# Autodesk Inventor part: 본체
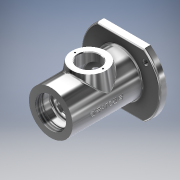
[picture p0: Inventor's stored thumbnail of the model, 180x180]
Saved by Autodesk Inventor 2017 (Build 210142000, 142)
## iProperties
Part Number: 본체
Material: 알루미늄 6061
Document SubType Name: Modeling
Designer: MRC
Density: 2.7 g/cm^3
Appearance: 알루미늄 - 평지
Mass: 701.516 g
Surface Area: 611.613 cm^2
Volume: 259.821 cm^3
Author: MRC
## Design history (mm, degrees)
sketch "스케치1"
  geometry: C1 r 32 at (0, 0); 1 further point
  constraints: 1 centre point, 1 coincident
  dimensions: "d0" = 64 diameter of C1
extrude "돌출1" new body sketch "스케치1" distance "d1" = 102; taper "d2" = 0 deg
sketch "스케치2"
  geometry: L1 (-58, 0)-(58, 0); L2 (-33.985, 47)-(33.985, 47); L3 (-33.985, -47)-(33.985, -47); A1 r 58 centre (0, 0) between (-33.985, 47) and (-33.985, -47); A2 r 58 centre (0, 0) between (33.985, -47) and (33.985, 47); 1 further point
  constraints: 6 end point, 6 point on circle, 2 centre point, 2 parallel, 1 coincident, 1 horizontal
  dimensions: "d4" = 47 distance between parallel lines of L1 L2; "d5" = 47 distance between parallel lines of L1 L3; "d6" = 58 radius of A1; "d7" = 58 radius of A2; "d8" = 67.97058 distance of L3.start L3.end
extrude "돌출2" join sketch "스케치2" distance "d9" = 10; taper "d10" = 0 deg
sketch "스케치3"
  geometry: C1 r 36 at (0, 0); 1 further point
  constraints: 1 centre point, 1 coincident
  dimensions: "d11" = 72 diameter of C1
extrude "돌출3" join sketch "스케치3" distance "d12" = 3; taper "d13" = 0 deg
sketch "스케치6"
  geometry: L1 (-36.77, -30.854)-(76.739, 64.392); L2 (0, 0)-(48, 0); C1 r 4 at (36.77, 30.854); C2 r 4 at (-36.77, -30.854); A1 r 48 centre (0, 0) between (48, 0) and (36.77, 30.854); 1 further point
  constraints: 4 end point, 3 centre point, 3 point on circle, 2 coincident, 2 point on line, 1 horizontal
  dimensions: "d27" = 96 diameter of A1; "d28" = 40 deg angle of L2 L1; "d29" = 8 diameter of C1; "d30" = 8 diameter of C2
extrude "돌출6" cut sketch "스케치6" stored distance "d31" = 4.4; taper "d32" = 0 deg
sketch "스케치10"
  geometry: C1 r 22.5 at (0, 0); 1 further point
  constraints: 1 centre point, 1 coincident
  dimensions: "d89" = 45 diameter of C1
extrude "돌출7" cut sketch "스케치10" distance "d90" = 8; taper "d91" = 0 deg
sketch "스케치11"
  geometry: C1 r 24 at (0, 0); 1 further point
  constraints: 1 centre point, 1 coincident
  dimensions: "d92" = 48 diameter of C1
extrude "돌출8" cut sketch "스케치11" distance "d93" = 3; taper "d94" = 0 deg
sketch "스케치12"
  geometry: C1 r 22.5 at (0, 0); 1 further point
  constraints: 1 centre point, 1 coincident
  dimensions: "d95" = 45 diameter of C1
extrude "돌출9" cut sketch "스케치12" distance "d96" = 11; taper "d97" = 0 deg
sketch "스케치13"
  geometry: C1 r 17.5 at (0, 0); 1 further point
  constraints: 1 centre point, 1 coincident
  dimensions: "d98" = 35 diameter of C1
extrude "돌출10" cut sketch "스케치13" distance "d99" = 2.25; taper "d100" = 0 deg
sketch "스케치14"
  geometry: C1 r 18.5 at (0, 0); 1 further point
  constraints: 1 centre point, 1 coincident
  dimensions: "d101" = 37 diameter of C1
extrude "돌출11" cut sketch "스케치14" distance "d102" = 1.75; taper "d103" = 0 deg
sketch "스케치15"
  geometry: C1 r 17.5 at (0, 0); 1 further point
  constraints: 1 centre point, 1 coincident
  dimensions: "d104" = 35 diameter of C1
extrude "돌출12" cut sketch "스케치15" distance "d105" = 11; taper "d106" = 0 deg
sketch "스케치16"
  geometry: C1 r 27 at (0, 0); 1 further point
  constraints: 1 centre point, 1 coincident
  dimensions: "d107" = 54 diameter of C1
extrude "돌출13" cut sketch "스케치16" distance "d108" = 38; taper "d109" = 0 deg
sketch "스케치17"
  geometry: C1 r 17.5 at (0, 0); 1 further point
  constraints: 1 centre point, 1 coincident
  dimensions: "d110" = 35 diameter of C1
extrude "돌출14" cut sketch "스케치17" distance "d111" = 11; taper "d112" = 0 deg
sketch "스케치18"
  geometry: C1 r 15 at (0, 0); 1 further point
  constraints: 1 centre point, 1 coincident
  dimensions: "d113" = 30 diameter of C1
extrude "돌출15" cut sketch "스케치18" distance "d114" = 5; taper "d115" = 0 deg
sketch "스케치19"
  geometry: L1 (-36, -13)-(36, -13) reference; L2 (0, -13)-(0, 1); L3 (0, 1)-(-20, 1); L4 (-32, 0)-(32, 0) reference; L5 (-20, 1)-(-30, -13); L6 (-30, -13)-(0, -13); 1 further point
  constraints: 8 end point, 1 collinear, 1 midpoint, 1 parallel, 1 point on line, 1 vertical
  dimensions: "d116" = 14 distance of L2.start L2.end; "d118" = 20 distance of L2.end L3.end; "d119" = 30 distance of L2.start L5.end
revolve "회전1" sketch "스케치19" stored, may be unused: angle "d120" = 90 deg
sketch "스케치20"
  geometry: C1 r 11 at (0, 0); 1 further point
  constraints: 1 centre point, 1 coincident
  dimensions: "d121" = 22 diameter of C1
extrude "돌출16" cut sketch "스케치20" distance "d122" = 2; taper "d123" = 0 deg
sketch "스케치21"
  geometry: C1 r 15 at (0, 0); 1 further point
  constraints: 1 centre point, 1 coincident
  dimensions: "d124" = 30 diameter of C1
extrude "돌출17" cut sketch "스케치21" distance "d125" = 8; taper "d126" = 0 deg
feature "스레드1" dims "d127" = 10, "d128" = 0
node "작업 평면1"
sketch "스케치22"
  geometry: L1 (32, 102)-(-32, 102) reference; L2 (-33.985, 0)-(33.985, 0) reference; C1 r 25 at (0, 46); 2 further points
  constraints: 1 centre point, 1 midpoint, 1 vertical alignment
  dimensions: "d130" = 50 diameter of C1; "d131" = 56 distance from line of L1 C1.centre
extrude "돌출18" join sketch "스케치22" stored distance "d132" = 8; taper "d133" = 10 deg
sketch "스케치23"
  geometry: C1 r 16 at (0, 0); 1 further point
  constraints: 1 centre point
  dimensions: "d134" = 32 diameter of C1
extrude "돌출19" cut sketch "스케치23" distance "d135" = 41; taper "d136" = 0 deg
sketch "스케치24" dims "d138" = 41
  geometry: L1 (33.985, 46)-(-33.985, 46) reference; C1 r 25 at (0, 0) reference; 4 further points
  constraints: 2 horizontal alignment, 1 coincident, 1 midpoint, 2 other
hole "구멍1" sketch "스케치24" at (-20.5, 0) diameter "d139" = 2.459; stored, may be unused: countersink angle "d143" = 90 deg, drill point angle "d145" = 118 deg; dims "d140" = 6, "d141" = 4, "d142" = 2, "d144" = 8
fillet "모깎기1" dims "d146" = 0.5, "d147" = 3, "d148" = 0.6
fillet "모깎기2" dims "d149" = 3
fillet "모깎기3" dims "d150" = 3
fillet "모깎기4" dims "d151" = 3
chamfer "모따기1" distance "d152" = 1; stored, may be unused: second distance "d153" = 2, angle "d154" = 45 deg
chamfer "모따기2" distance "d155" = 1; stored, may be unused: second distance "d156" = 2, angle "d157" = 45 deg
chamfer "모따기3" distance "d158" = 1; stored, may be unused: second distance "d159" = 2, angle "d160" = 45 deg
chamfer "모따기4" distance "d161" = 1; stored, may be unused: second distance "d162" = 2, angle "d163" = 45 deg
fillet "모깎기5" dims "d164" = 3
fillet "모깎기6" dims "d165" = 3
fillet "모깎기7" dims "d166" = 3
chamfer "모따기5" distance "d167" = 1; stored, may be unused: second distance "d168" = 2, angle "d169" = 45 deg
node "작업 평면2"
sketch "스케치25"
  geometry: L1 (-47, -10)-(47, -10) reference; 2 further points
  constraints: 1 vertical alignment, 1 other
  dimensions: "d171" = 62 distance from line of L1 point (0, 52)
feature "엠보싱1" sketch "스케치25" dims "d172" = 0.5, "d173" = 0
chamfer "모따기6" distance "d174" = 0.7; stored, may be unused: second distance "d175" = 2, angle "d176" = 30 deg
node "솔리드1"
mirror "미러1"
other parameters: "d3" = 116, "d34" = 4, "d35" = 4, "d36" = 4, "d129" = 38, "d170" = 85.25
